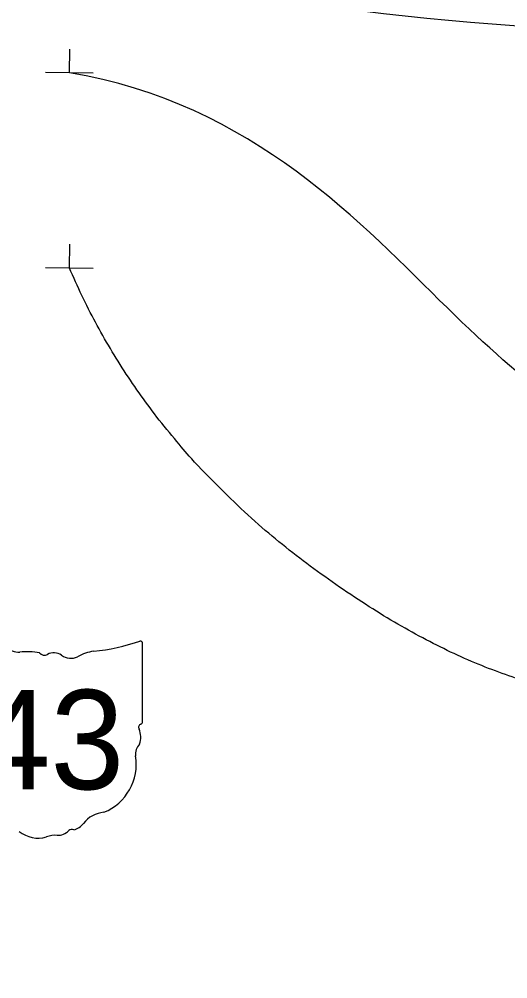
# Model space of a CAD drawing. Extents: x -202 to 1556, y 0 to 676.
# Drawn here: x 191.4 to 228.3, y 37.1 to 109.6 of the extents above; entities that cross this region are included whole.
import ezdxf

# ---------------------------------------------------------------- set-up
doc = ezdxf.new("R2010")
doc.units = 0
for name, color, linetype in [('GM_X_City_Street', 7, 'Continuous'), ('GM_X_Major_River_Text', 7, 'Continuous'), ('GM_X_Minor_Lake', 7, 'Continuous'), ('SH_Data', 7, 'Continuous')]:
    doc.layers.add(name, color=color, linetype=linetype)

msp = doc.modelspace()

# ---------------------------------------------------------------- linework, layer by layer
at = {"layer": 'GM_X_City_Street'}
for p, q in [((200.72, 56.535), (200.72, 62.424)), ((200.719, 56.537), (200.72, 56.535))]:
    msp.add_line(p, q, dxfattribs=at)
for centre, radius, start, end in [((195.437, 77.491), 15.728, 275.84447, 288.90645), ((200.556, 62.448), 0.165, 351.86209, 97.738), ((191.413, 63.451), 1.667, 231.61951, 271.11188), ((191.965, 55.825), 5.983, 80.48669, 94.98827), ((193.324, 62.033), 0.481, 219.79206, 297.10237), ((194.029, 60.732), 1, 54.46668, 119.14113), ((197.443, 58.707), 3.164, 97.34618, 120.76885), ((195.32, 62.517), 1.203, 233.85621, 294.82819), ((200.544, 56.512), 0.177, 289.60381, 7.73413), ((200.682, 56.103), 0.256, 107.94398, 210.33697), ((199.057, 55.358), 1.534, 340.03296, 23.64957), ((201.312, 54.071), 1.116, 136.8065, 186.92959), ((196.318, 53.322), 3.934, 292.30889, 8.98584), ((197.977, 47.534), 2.155, 94.40312, 142.57675), ((195.247, 49.603), 1.271, 282.87319, 323.27711), ((192.837, 49.989), 2.255, 230.70037, 286.29184), ((194.14, 46.097), 1.853, 85.69512, 111.20995), ((194.304, 49.146), 1.201, 268.77702, 315.54927), ((195.391, 48.056), 0.338, 65.75173, 132.64842)]:
    msp.add_arc(centre, radius, start, end, dxfattribs=at)
at = {"layer": 'GM_X_Major_River_Text'}
for p, q in [((194.941, 52.515), (194.941, 52.53)), ((194.943, 52.53), (194.943, 52.528)), ((194.943, 52.525), (194.943, 52.515)), ((194.949, 52.529), (194.949, 52.529)), ((194.95, 52.519), (194.95, 52.519))]:
    msp.add_line(p, q, dxfattribs=at)
for points in [[(194.94, 52.517), (194.94, 52.518), (194.941, 52.518)], [(194.941, 52.516), (194.94, 52.517), (194.94, 52.517)], [(194.94, 52.517), (194.94, 52.517), (194.94, 52.517)], [(194.941, 52.53), (194.941, 52.531), (194.941, 52.531)], [(194.941, 52.531), (194.941, 52.531), (194.942, 52.531)], [(194.941, 52.53), (194.941, 52.53), (194.941, 52.53)], [(194.941, 52.53), (194.941, 52.53), (194.941, 52.53)], [(194.941, 52.528), (194.942, 52.529), (194.942, 52.529)], [(194.941, 52.527), (194.941, 52.527), (194.941, 52.528)], [(194.941, 52.525), (194.941, 52.526), (194.941, 52.527)], [(194.942, 52.524), (194.942, 52.524), (194.941, 52.525)], [(194.941, 52.518), (194.941, 52.518), (194.941, 52.518)], [(194.941, 52.518), (194.941, 52.518), (194.941, 52.518)], [(194.941, 52.518), (194.941, 52.518), (194.941, 52.518)], [(194.941, 52.518), (194.942, 52.517), (194.942, 52.517)], [(194.942, 52.515), (194.942, 52.515), (194.941, 52.516)], [(194.941, 52.516), (194.941, 52.516), (194.941, 52.516)], [(194.941, 52.516), (194.941, 52.516), (194.941, 52.516)], [(194.942, 52.515), (194.941, 52.515), (194.941, 52.515)], [(194.941, 52.515), (194.941, 52.515), (194.941, 52.515)], [(194.941, 52.515), (194.941, 52.515), (194.941, 52.515)], [(194.941, 52.515), (194.941, 52.515), (194.941, 52.515)], [(194.942, 52.531), (194.942, 52.531), (194.942, 52.531)], [(194.942, 52.531), (194.942, 52.531), (194.942, 52.53)], [(194.942, 52.529), (194.943, 52.53), (194.944, 52.53)], [(194.942, 52.53), (194.942, 52.53), (194.942, 52.53)], [(194.942, 52.53), (194.943, 52.53), (194.943, 52.53)], [(194.943, 52.523), (194.943, 52.523), (194.942, 52.524)], [(194.942, 52.517), (194.943, 52.517), (194.943, 52.517)], [(194.944, 52.515), (194.943, 52.515), (194.942, 52.515)], [(194.943, 52.515), (194.943, 52.515), (194.942, 52.515)], [(194.942, 52.515), (194.942, 52.515), (194.942, 52.515)], [(194.942, 52.515), (194.942, 52.515), (194.942, 52.515)], [(194.943, 52.528), (194.943, 52.529), (194.944, 52.529)], [(194.944, 52.528), (194.943, 52.528), (194.943, 52.528)], [(194.943, 52.528), (194.943, 52.527), (194.943, 52.527)], [(194.943, 52.527), (194.943, 52.526), (194.943, 52.525)], [(194.944, 52.527), (194.943, 52.526), (194.943, 52.525)], [(194.943, 52.525), (194.943, 52.525), (194.944, 52.525)], [(194.945, 52.522), (194.944, 52.523), (194.943, 52.523)], [(194.943, 52.517), (194.944, 52.516), (194.945, 52.516)], [(194.943, 52.515), (194.943, 52.515), (194.943, 52.515)], [(194.944, 52.53), (194.945, 52.531), (194.946, 52.531)], [(194.944, 52.529), (194.944, 52.53), (194.945, 52.53)], [(194.945, 52.529), (194.944, 52.529), (194.944, 52.528)], [(194.945, 52.528), (194.944, 52.528), (194.944, 52.527)], [(194.944, 52.525), (194.945, 52.524), (194.945, 52.524)], [(194.945, 52.515), (194.944, 52.515), (194.944, 52.515)], [(194.945, 52.53), (194.945, 52.531), (194.946, 52.531)], [(194.946, 52.529), (194.945, 52.529), (194.945, 52.529)], [(194.946, 52.529), (194.945, 52.529), (194.945, 52.528)], [(194.945, 52.524), (194.946, 52.524), (194.947, 52.523)], [(194.946, 52.522), (194.945, 52.522), (194.945, 52.522)], [(194.945, 52.516), (194.946, 52.516), (194.946, 52.517)], [(194.947, 52.515), (194.946, 52.515), (194.945, 52.515)], [(194.946, 52.531), (194.947, 52.531), (194.947, 52.531)], [(194.946, 52.531), (194.946, 52.531), (194.947, 52.531)], [(194.947, 52.529), (194.947, 52.529), (194.946, 52.529)], [(194.947, 52.529), (194.946, 52.529), (194.946, 52.529)], [(194.947, 52.521), (194.947, 52.521), (194.946, 52.522)], [(194.946, 52.517), (194.947, 52.517), (194.948, 52.517)], [(194.947, 52.531), (194.948, 52.531), (194.948, 52.53)], [(194.947, 52.531), (194.947, 52.531), (194.947, 52.531)], [(194.947, 52.531), (194.947, 52.531), (194.948, 52.531)], [(194.948, 52.529), (194.948, 52.529), (194.947, 52.529)], [(194.948, 52.529), (194.948, 52.529), (194.947, 52.529)], [(194.947, 52.529), (194.947, 52.529), (194.947, 52.529)], [(194.947, 52.523), (194.947, 52.523), (194.948, 52.523)], [(194.948, 52.52), (194.948, 52.521), (194.947, 52.521)], [(194.949, 52.516), (194.948, 52.515), (194.947, 52.515)], [(194.948, 52.531), (194.948, 52.531), (194.948, 52.53)], [(194.948, 52.53), (194.949, 52.53), (194.949, 52.53)], [(194.948, 52.53), (194.949, 52.53), (194.949, 52.53)], [(194.949, 52.528), (194.949, 52.528), (194.948, 52.529)], [(194.949, 52.528), (194.948, 52.528), (194.948, 52.529)], [(194.948, 52.529), (194.948, 52.529), (194.948, 52.529)], [(194.948, 52.523), (194.949, 52.522), (194.949, 52.522)], [(194.949, 52.519), (194.949, 52.52), (194.948, 52.52)], [(194.948, 52.518), (194.949, 52.518), (194.949, 52.519)], [(194.948, 52.517), (194.948, 52.517), (194.948, 52.518)], [(194.949, 52.53), (194.949, 52.53), (194.949, 52.53)], [(194.949, 52.53), (194.95, 52.53), (194.95, 52.53)], [(194.949, 52.53), (194.949, 52.53), (194.949, 52.53)], [(194.949, 52.53), (194.949, 52.53), (194.949, 52.53)], [(194.949, 52.53), (194.949, 52.53), (194.949, 52.53)], [(194.949, 52.53), (194.949, 52.53), (194.949, 52.529)], [(194.949, 52.529), (194.949, 52.529), (194.949, 52.529)], [(194.949, 52.529), (194.949, 52.529), (194.949, 52.529)], [(194.949, 52.529), (194.949, 52.529), (194.949, 52.529)], [(194.949, 52.529), (194.949, 52.528), (194.949, 52.528)], [(194.95, 52.528), (194.949, 52.528), (194.949, 52.528)], [(194.949, 52.528), (194.949, 52.528), (194.949, 52.528)], [(194.949, 52.522), (194.95, 52.522), (194.95, 52.521)], [(194.95, 52.517), (194.95, 52.517), (194.949, 52.516)], [(194.95, 52.53), (194.95, 52.53), (194.95, 52.529)], [(194.95, 52.529), (194.95, 52.529), (194.95, 52.529)], [(194.95, 52.529), (194.95, 52.529), (194.95, 52.529)], [(194.95, 52.529), (194.95, 52.529), (194.95, 52.528)], [(194.95, 52.528), (194.95, 52.528), (194.95, 52.528)], [(194.95, 52.528), (194.95, 52.528), (194.95, 52.528)], [(194.95, 52.521), (194.95, 52.52), (194.95, 52.519)], [(194.95, 52.519), (194.95, 52.518), (194.95, 52.517)]]:
    msp.add_open_spline(points, degree=2, dxfattribs=at)
at = {"layer": 'GM_X_Minor_Lake'}
for p, q in [((195.204, 105.522), (195.226, 107.322)), ((197.004, 105.5), (193.404, 105.544)), ((195.204, 90.785), (195.226, 92.585)), ((197.004, 90.763), (193.404, 90.808))]:
    msp.add_line(p, q, dxfattribs=at)
at = {"layer": 'SH_Data'}
msp.add_circle((192.681, 118.45), 90, dxfattribs=at)
for points, degree in [([(318.25, 98.638), (296.149, 103.629), (275.174, 107.573), (247.729, 107.512), (203.85, 110.623), (195.4, 115.77)], 3), ([(284.719, 64.428), (256.931, 61.674), (237.168, 76.821), (226.214, 84.276), (208.972, 103.332), (195.204, 105.522)], 3), ([(266.381, 41.591), (266.381, 46.465), (249.203, 58.245), (227.223, 58.245), (200.993, 77.269), (195.204, 90.785)], 2)]:
    msp.add_open_spline(points, degree=degree, dxfattribs=at)

# ---------------------------------------------------------------- texts
at = {"layer": 'GM_X_City_Street'}
msp.add_text('43', height=7.5, dxfattribs=at).set_placement((188.189, 51.428))

doc.saveas('drawing.dxf')
